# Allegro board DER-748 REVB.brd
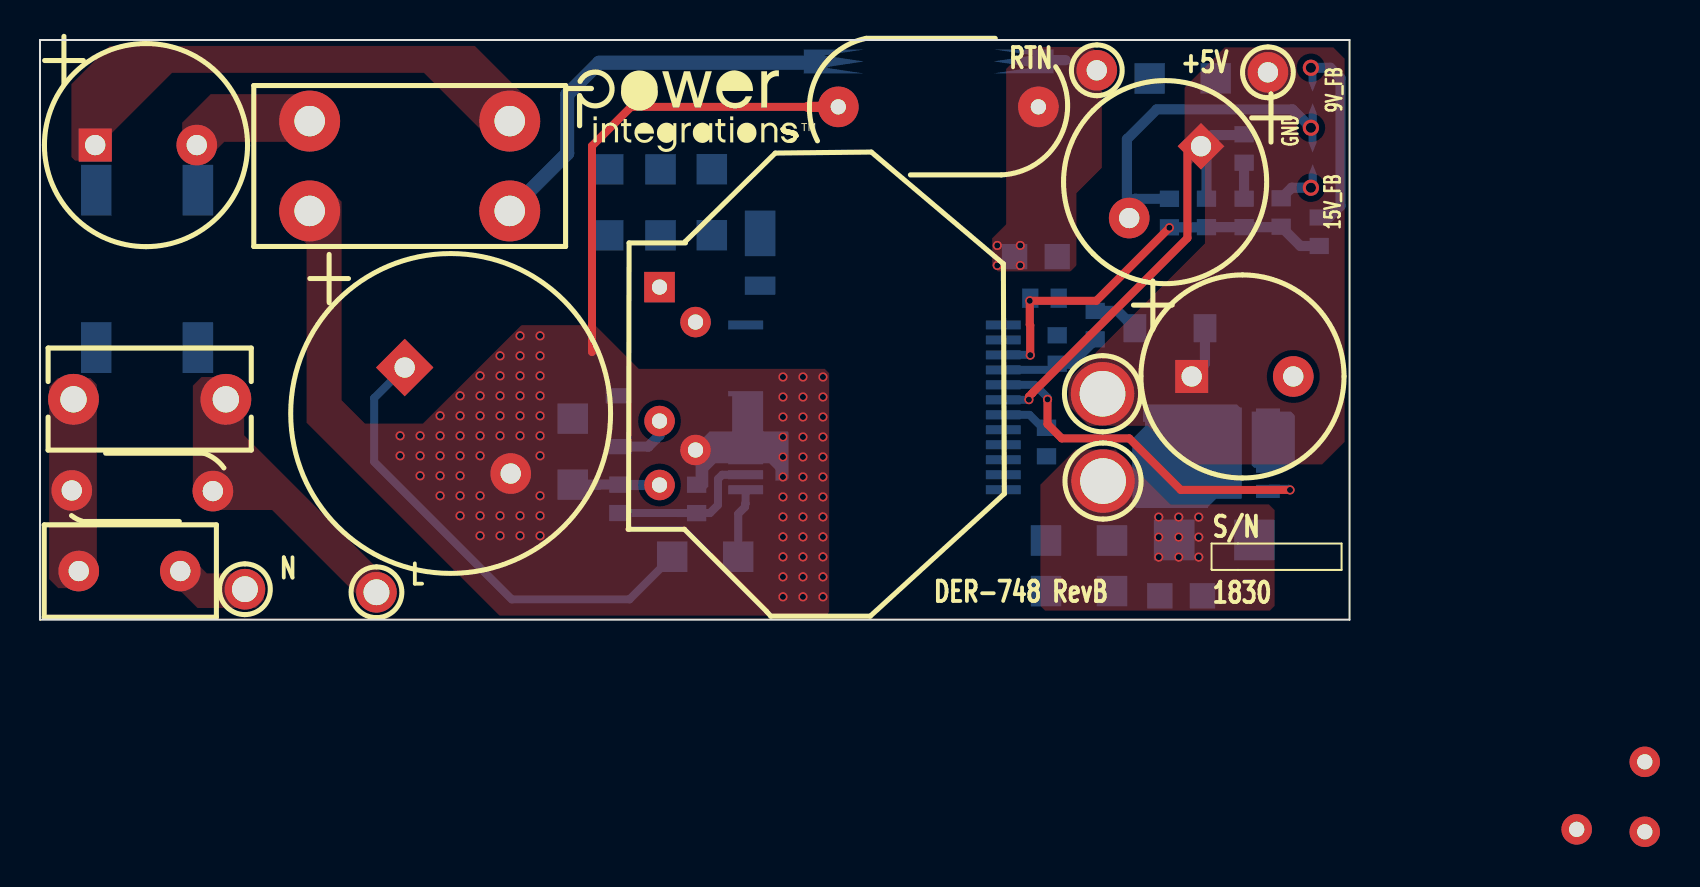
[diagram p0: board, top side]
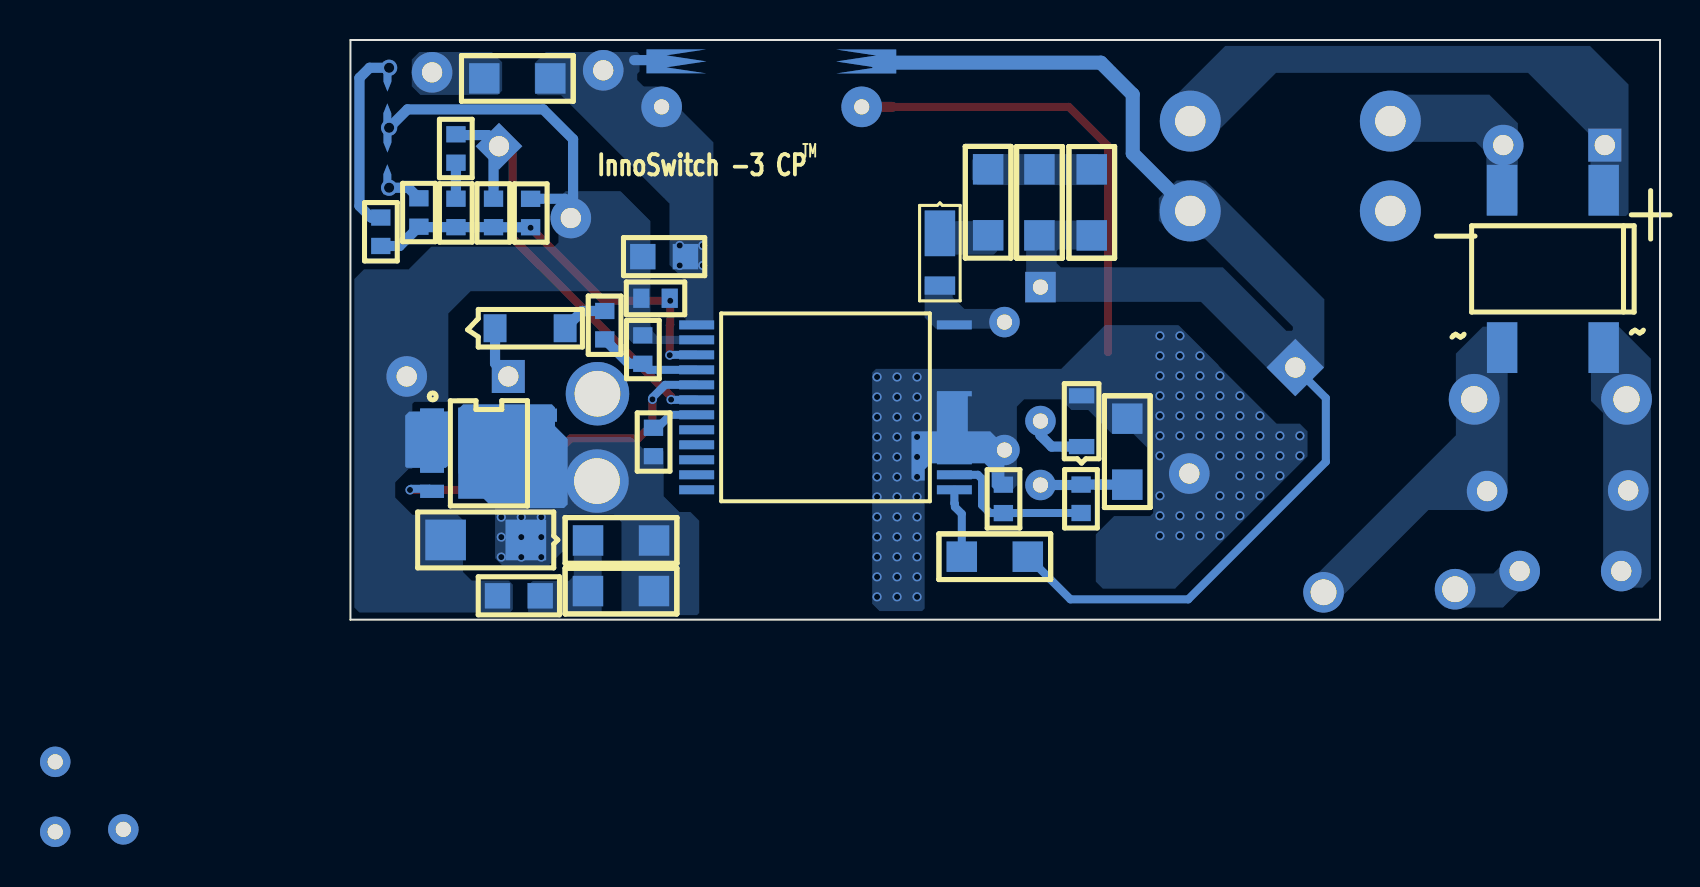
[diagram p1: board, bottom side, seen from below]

Outline 65.5 x 29 mm; copper layers: TOP, BOTTOM. Coordinates in mm from the lower left corner of the outline.
Outline path: 0,29 65.5,29 65.5,0 0,0 0,29

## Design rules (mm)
constraint set DEFAULT: min track width 0.508

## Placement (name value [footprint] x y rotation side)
BR1  DF206ST-G  [PISMDDFS]  2.82 21.43 180 bottom
C1  47 nF  [PI_NP395X200LS300D040]  9.3 11.02 180 top
C3  56 uF  [PIPOLCAPCLYD16D16H7P5LS040]  18.24 12.61 315 top
C5  0.47 uF  [PISMC0603]  32.84 5.33 90 bottom
C6  22 uf  [PISMC1206]  26.64 6.75 90 bottom
C7  2.2 nF  [PINPCAPRAD374X275LS394D030]  39.93 25.65 0 top
C8  2.2 nF  [PISMC0805]  56.01 1.19 0 bottom
C9  2.2 uF  [PISMC0603]  50.88 12.8 90 bottom
C11  330 pF  [PISMC0603]  50.95 16.08 180 bottom
C12  4.7 nF  [PISMC0603]  60.22 21.06 270 bottom
C13  10 uF  [PISMC1206]  58.8 27.08 180 bottom
C14  560 uF  [PIPOLCAPCYLD400LS200040]  58.07 23.68 225 top
C15  560 uF  [PIPOLCAPCYLD400LS200040]  57.6 12.17 0 top
C17  27 uF  [PIPOLCAPCYLD400LS200040]  2.76 23.74 0 top
C18  470 pF  [PISMC1206]  28.42 19.23 90 bottom
D1  DFLR1600  [PISMDDFLR120012]  36.02 19.35 90 bottom
D2  BAV21WS-7-F  [PISMSOD323]  28.93 8.66 90 bottom
D4  STPS2H100AY  [PISMDSMA]  56.73 3.99 0 bottom
F1  1 A  [PI_RST_MICROFUSE]  7.02 2.43 180 top
FL1  Hole_90  [PI_HOLE_70MIL]  53.14 11.28 0 top
FL2  Hole_90  [PI_HOLE_70MIL]  53.17 6.91 0 top
L1  10 mH  [PI_IND_4P_590X295LS394X177D060]  13.51 24.92 180 top
NOREF  -  []  65.5 0 90 top
NOREF#2  -  []  26.34 27.28 0 top
NOREF#3  -  []  -150.78 54.23 0 top
NOREF#4  -  []  0 29 0 top
NOREF#5  -  []  -228.6 -144.78 0 top
Q3  BSC028N06LS3GATMA1  [PI_SM_PG-TDSON-8]  61.42 10.23 270 bottom
R5  51  [PISMR1206]  33.6 22.53 270 bottom
R8  10 k  [PISMR0603]  28.96 6.76 270 bottom
R10  47  [PISMR0603]  50.34 8.18 90 bottom
R13  13  [PISMR1206]  50.32 3.96 0 bottom
R14  100 k  [PISMR0603]  58.34 21.06 270 bottom
R15  33 K  [PISMR0603]  56.49 19.63 90 bottom
R16  0.005  [PISMR0805]  50.88 18.16 180 bottom
R19  2.2M  [PISMR1206]  31.62 3.15 0 bottom
R21  200 k  [PISMR1206]  31.04 19.23 90 bottom
R22  32.4 k  [PISMR0603]  63.98 18.69 90 bottom
R23  12.4 k  [PISMR0603]  62.08 19.66 90 bottom
R24  0.0  [PISMR0603]  60.22 24.28 270 bottom
R25  1 k  [PISMR0603]  52.78 15.44 270 bottom
R26  13  [PISMR1206]  50.32 1.43 0 bottom
RV1  275 Vac  [PIDISC350X160LS210X140040]  8.65 6.43 210 top
T2  RM8  [PI_BOBBIN_RM8_8P]  30.99 16.64 0 top
TP1  L  [PITPKEYSTONE100X100]  16.83 1.37 0 top
TP2  N  [PITPKEYSTONE100X100]  10.25 1.52 0 top
TP10  RET  [PITPKEYSTONE100X100]  52.86 27.48 0 top
TP11  +5V  [PITPKEYSTONE100X100]  61.42 27.38 0 top
U1  INN3268C  [PI_IC_INSOP_24D]  48.18 14.75 180 bottom
VR1  MMSZ5245B  [PI_SM_SOD-123_12]  58.27 14.58 180 bottom

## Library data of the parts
BR1 = DIODE BRIDGE_+-~~
C1 C5-C9 C11-C13 C18 = CAP NP
C3 = CAP POL: alternate symbols: (pipolcapclyd16d16h7p5ls040h)
C14 C15 = CAP POL
C17 = CAP POL: alternate symbols: (pipolcapclyd400x675ls200040h)
D1 D2 = DIODE
D4 = DIODE SCHOTTKY
F1 = FUSE: alternate symbols: (pirstmicrofusehoz)
FL1 FL2 = FlyingLead
L1 = INDUCTOR_4P_revD
Q3 = FET_N_TSDSON-8
R5 R8 R10 R13-R16 R19 R21-R26 = R
RV1 = VARISTOR: alternate symbols: (pi_disc_354x220_ls220x10_040_h)
T2 = BRM8_8P/6-2
TP1 TP2 TP10 TP11 = TESTPOINT
U1 = DEV_InSOP_0
VR1 = DIODE_ZENER

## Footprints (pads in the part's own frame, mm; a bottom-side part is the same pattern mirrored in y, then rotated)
PI_BOBBIN_RM8_8P
  rect 1.524x1.524 hole 0.762: 1(0,0)
  round 1.524 hole 0.762: 2(1.8,-1.75) 3(45.872,-27.127) 4(0,-6.7) 5(1.8,-8.15) 6(0,-9.9) 7(49.278,-27.249) 8(49.278,-23.749)
PI_HOLE_70MIL
  round 3.175 hole 2.286: 1(0,0.025)
PI_IC_INSOP_24D
  rect 1.75x0.45 smd: 1(0,0) 2(0,-0.75) 3(0,-1.5) 4(0,-2.25) 5(0,-3) 6(0,-3.75) 7(0,-4.5) 8(0,-5.25) 9(0,-6) 10(0,-6.75) 11(0,-7.5) 12(0,-8.25) 13(12.89,-8.25) 14(12.89,-7.5) 15(12.89,-6.75) 24(12.89,0)
  custom 0.438x0.438 smd: 16(12.89,-4.67)
PI_IND_4P_590X295LS394X177D060
  round 3.048 hole 1.524: 1(0.025,-0.025) 2(0.025,4.47) 3(-9.982,4.47) 4(-9.982,-0.025)
PI_NP395X200LS300D040
  round 2.54 hole 1.321: 1(0,0) 2(7.62,0)
PI_RST_MICROFUSE
  round 2.032 hole 1.016: 1(0,0) 2(5.08,0)
PI_SM_PG-TDSON-8
  rect 0.66x1.194 smd: 1(0,0) 2(1.27,0) 3(2.54,0) 4(3.81,0) 5(3.81,5.65) 6(2.54,5.65) 7(1.27,5.65) 8(0,5.65)
PI_SM_SOD-123_12
  rect 1.143x1.397 smd: 1(0,0) 2(3.505,0)
PIDISC350X160LS210X140040
  round 2.032 hole 1.016: 1(0,0) 2(6.096,-3.556)
PINPCAPRAD374X275LS394D030
  round 2.032 hole 0.762: 1(0,0) 2(10.008,0)
PIPOLCAPCLYD16D16H7P5LS040
  rect 2.032x2.032 hole 1.016: 1(0,0)
  round 2.032 hole 1.016: 2(7.5,0)
PIPOLCAPCYLD400LS200040
  rect 1.651x1.651 hole 1.016: 1(0,0)
  round 2.032 hole 1.016: 2(5.08,0)
PISMC0603
  rect 0.813x0.965 smd: 1(0,0) 2(1.422,0)
PISMC0805
  rect 1.27x1.27 smd: 1(0,0) 2(2.134,0)
PISMC1206
  rect 1.524x1.524 smd: 1(0,0) 2(3.302,0)
PISMDDFLR120012
  rect 2.286x1.524 smd: 1(-0.025,0)
  rect 0.914x1.524 smd: 2(-2.642,0)
PISMDDFS
  rect 1.524x2.54 smd: 1(0,0.051) 2(-5.08,0.051) 3(0,-7.823) 4(-5.08,-7.823)
PISMDSMA
  rect 2.032x2.032 smd: 1(0,0) 2(4.013,0)
PISMR0603
  rect 0.813x0.965 smd: 1(0,0) 2(1.422,0)
PISMR0805
  rect 1.27x1.27 smd: 1(0,0) 2(2.134,0)
PISMR1206
  rect 1.524x1.524 smd: 1(0,0) 2(3.302,0)
PISMSOD323
  rect 0.762x1.27 smd: 1(0,0) 2(2.54,0)
PITPKEYSTONE100X100
  round 2.032 hole 1.295: 1(0,0)

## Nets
GND_POWER: C8.2 C9.2 C11.1 C14.2 C15.2 D4.2 Q3.1(S1) R15.2 R16.1 U1.2
GND_SIGNAL: C3.2 C5.2 C6.2 C7.1 D2.2 L1.2 T2.5 U1.16
D6: Q3.6
D7: Q3.7
D8: Q3.8
NC8: U1.8
NC9: U1.9
NC10: U1.10
NC11: U1.11
NC12: U1.12
NC15: U1.15
S2: Q3.2
S3: Q3.3
N11018979: C13.1 C14.1 C15.1 FL1.1 R14.1 R24.1 TP11.1 U1.6 VR1.1
N11018987: C7.2 C13.2 R16.2 TP10.1 U1.1
N11019023: R10.2 U1.7
N11019027: D4.1 FL2.1 Q3.5 R10.1 R13.1 R26.1
N11019129: Q3.4 U1.5
N11019153: D1.1 R5.2
N11019263: BR1.2 C17.2 L1.1
N11019293: C5.1 R8.2 U1.14
N11019397: BR1.4 C1.1 RV1.1 TP1.1
N11019401: C8.1 R13.2 R26.2
N11019569: C6.1 R8.1 T2.6
N11019593: R19.2 U1.13(VPIN)
N11019613: C3.1 C18.1 L1.3 R19.1 R21.1 T2.1
N11019673: BR1.3 C1.2 F1.2 RV1.2
N11019681: BR1.1 C17.1 L1.4
N11019743: C11.2 C12.2 R14.2 R15.1 R22.1 R23.1 U1.3
N11020702: C18.2 R5.1 R21.2
N11020753: D1.2 T2.2 U1.24
N11026403: F1.1 TP2.1
N11053934: D2.1 T2.4
N11096846: R22.2
N11102317: R23.2
N11111738: C12.1 R24.2
N11113310: C9.1 R25.2 U1.4
N11114484: R25.1 VR1.2

Pads without a net: T2 3 7 8

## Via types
v1: diameter 0.813, hole 0.508, TOP to BOTTOM, 3 vias
v2: diameter 0.457, hole 0.305, TOP to BOTTOM, 105 vias

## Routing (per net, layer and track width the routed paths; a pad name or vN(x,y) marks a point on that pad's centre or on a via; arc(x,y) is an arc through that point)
GND_POWER: length 17
  BOTTOM w0.508: v1(63.57,24.61) 62.65,25.53 55.85,25.53 54.37,24.04 54.37,20.21 C14.2 54.48,20.75 54.78,21.05 R15.2
GND_SIGNAL: length 23.4
  TOP w0.4: 38.4,25.65 29.57,25.65 27.61,23.7 27.61,13.39
  TOP w0.508: 38.4,25.65 C7.1
  vias: v2(18.01,9.2) v2(18.01,8.2) v2(19.01,9.2) v2(19.01,8.2) v2(19.01,7.2) v2(20.01,10.2) v2(20.01,9.2) v2(20.01,8.2) v2(20.01,7.2) v2(20.01,6.2) v2(21.01,11.2) v2(21.01,10.2) v2(21.01,9.2) v2(21.01,8.2) v2(21.01,7.2) v2(21.01,6.2) v2(21.01,5.2) v2(22.01,12.2) v2(22.01,11.2) v2(22.01,10.2) v2(22.01,9.2) v2(22.01,8.2) v2(22.01,6.2) v2(22.01,5.2) v2(22.01,4.2) v2(23.01,13.2) v2(23.01,12.2) v2(23.01,11.2) v2(23.01,10.2) v2(23.01,9.2) v2(23.01,5.2) v2(23.01,4.2) v2(24.01,14.2) v2(24.01,13.2) v2(24.01,12.2) v2(24.01,11.2) v2(24.01,10.2) v2(24.01,9.2) v2(24.01,5.2) v2(24.01,4.2) v2(25.01,14.2) v2(25.01,13.2) v2(25.01,12.2) v2(25.01,11.2) v2(25.01,10.2) v2(25.01,9.2) v2(25.01,8.2) v2(25.01,6.2) v2(25.01,5.2) v2(25.01,4.2) v2(37.16,12.14) v2(37.16,11.14) v2(37.16,10.14) v2(37.16,9.14) v2(37.16,8.14) v2(37.16,7.14) v2(37.16,6.14) v2(37.16,5.14) v2(37.16,4.14) v2(37.16,3.14) v2(37.16,2.14) v2(37.16,1.14) v2(38.16,12.14) v2(38.16,11.14) v2(38.16,10.14) v2(38.16,9.14) v2(38.16,8.14) v2(38.16,7.14) v2(38.16,6.14) v2(38.16,5.14) v2(38.16,4.14) v2(38.16,3.14) v2(38.16,2.14) v2(38.16,1.14) v2(39.16,12.14) v2(39.16,11.14) v2(39.16,10.14) v2(39.16,9.14) v2(39.16,8.14) v2(39.16,7.14) v2(39.16,6.14) v2(39.16,5.14) v2(39.16,4.14) v2(39.16,3.14) v2(39.16,2.14) v2(39.16,1.14)
N11018979: length 25.7
  TOP w0.4: v2(49.46,11.01) 49.46,11.16 49.63,11.33 49.63,11.34 57.39,19.09 57.39,23.67 57.41,23.68 C14.1
  BOTTOM w0.4: U1.6 49.45,11 v2(49.46,11.01)
  BOTTOM w0.508: VR1.1 58.27,12.82 57.62,12.17 C15.1 ; R24.1 60.17,24.28 60.13,24.24 58.63,24.24 C14.1 58.34,23.41 R14.1
N11018987: length 1.2
  BOTTOM w0.508: 50.09,27.99 51.31,27.99
  vias: v2(47.88,18.72) v2(47.88,17.72) v2(49.03,18.72) v2(49.03,17.72)
N11019023: length 2.4
  BOTTOM w0.4: U1.7 49.49,10.25 50.14,9.6 R10.2
N11019027:
  vias: v2(55.96,5.13) v2(55.96,4.13) v2(55.96,3.13) v2(56.96,5.13) v2(56.96,4.13) v2(56.96,3.13) v2(57.96,5.13) v2(57.96,4.13) v2(57.96,3.13)
N11019129: length 18.5
  TOP w0.4: v2(50.39,11.02) 50.39,9.78 51.1,9.07 54.48,9.07 57.06,6.49 v2(62.52,6.49)
  BOTTOM w0.4: v2(50.39,11.02) 50.39,11.11 49.76,11.75 U1.5 ; v2(62.52,6.49) 62.47,6.55 61.54,6.55 Q3.4
N11019293: length 7.9
  BOTTOM w0.4: U1.14 34.12,7.25 33.91,7.04 33.91,5.73 33.51,5.33 C5.1 31.91,5.33 31.9,5.34 R8.2
N11019569: length 4.4
  BOTTOM w0.508: C6.1 27.91,6.75 27.92,6.76 R8.1 28.98,6.74 T2.6
N11019593: length 3.5
  BOTTOM w0.4: U1.13 35.29,5.82 35.27,5.79 35.27,5.64 34.92,5.3 R19.2
N11019613: length 44.4
  BOTTOM w0.4: C3.1 16.71,11.09 16.71,7.9 23.6,1.02 29.49,1.02 R19.1
  BOTTOM w0.7: L1.3 26.37,23.32 26.37,26.27 27.97,27.86 39.14,27.86
N11019743: length 20.5
  TOP w0.4: v2(49.53,13.23) 49.53,14.73 49.5,14.76 v2(49.5,15.95) 52.84,15.95 v2(56.49,19.61)
  BOTTOM w0.4: U1.3 49.52,13.25 v2(49.53,13.23)
  BOTTOM w0.508: R15.1 58.14,19.63 58.14,19.64 R14.2 60.1,19.64 C12.2 62.06,19.64 R23.1 63.04,18.69 R22.1
N11053934: length 3
  BOTTOM w0.508: D2.1 30.43,8.66 30.99,9.22 T2.4
N11096846: length 9.4
  BOTTOM w0.508: v1(63.57,27.61) 64.54,27.61 65.05,27.1 65.05,20.7 64.47,20.12 R22.2
N11102317: length 1.7
  BOTTOM w0.508: v1(63.57,21.61) 62.61,21.61 R23.2
N11111738: length 1.8
  BOTTOM w0.508: C12.1 R24.2
N11113310: length 5.2
  BOTTOM w0.4: U1.4 50.57,12.5 C9.1
  BOTTOM w0.508: C9.1 51.56,12.8 R25.2
N11114484: length 2.3
  BOTTOM w0.508: VR1.2 53.9,15.44 R25.1

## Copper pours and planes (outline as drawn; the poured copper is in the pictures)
GND_POWER on BOTTOM (solid shape): 62.76,10.21 62.76,7.67 62.69,7.59 60.73,7.59 60.6,7.72 60.6,10.41 62.56,10.41
GND_POWER on BOTTOM (solid shape): 62.01,8.63 62.02,8.63 62.02,7.36 60.82,7.36 60.82,10.56 62.01,10.56
GND_POWER on BOTTOM: 62.4,5.25 63.26,6.11 63.26,6.87 62.59,7.54 62.41,7.54 62.41,10.79 62.31,10.9 60.6,10.9 60.6,15.32 59.49,16.43 51.92,16.43 51.64,16.15 51.64,14.1 51.33,13.79 47.88,13.79 47.85,13.82 47.85,14.12 47.93,14.2 50.16,14.2 50.47,14.5 50.47,14.67 50.5,14.69 50.5,19.94 51.99,21.44 54.74,21.44 55.09,21.08 55.09,18.87 55.31,18.66 61.46,18.66 62.59,17.53 64.82,17.53 65.3,17.04 65.3,0.61 65.05,0.36 57.53,0.36 57.38,0.51 57.38,1.75 57.58,1.96 59.44,1.96 59.87,2.39 59.87,4.98 60.13,5.25
GND_SIGNAL on BOTTOM (solid shape): 37.44,9.37 37.44,7.06 37.34,6.96 36.78,6.96 36.78,7.52 36.47,7.82 33.78,7.82 33.43,7.47 33.43,6.65 33.3,6.53 32.94,6.53 32.79,6.68 32.79,8.71 33.5,9.42 37.39,9.42
GND_SIGNAL on TOP: 39.47,12.32 39.47,0.38 39.29,0.2 22.99,0.2 13.34,9.86 13.34,18.8 12.04,20.09 12.04,21.08 12.57,21.62 14.38,21.62 15.09,20.9 15.09,10.97 16.26,9.8 19.15,9.8 24.08,14.73 27.76,14.73 29.95,12.55 39.24,12.55
GND_SIGNAL on BOTTOM: 33.43,8.36 33.43,6.65 33.25,6.48 32.41,6.48 32.17,6.72 32.17,10.66 31.8,11.02 29.97,11.02 29.44,10.49 28.6,10.49 27.41,9.3 26.34,9.3 25.35,8.31 25.35,5.33 25.5,5.18 27.3,5.18 28.22,4.27 28.22,1.91 27.86,1.55 24.26,1.55 17.63,8.18 17.63,9.42 18.01,9.8 19.18,9.8 22.07,12.7 22.07,12.73 24.08,14.73 27.76,14.73 29.95,12.55 39.22,12.55 39.41,12.36 39.41,0.8 39.04,0.43 36.91,0.43 36.78,0.56 36.78,8.51 36.53,8.76 33.83,8.76
D8 on BOTTOM (solid shape): 60.11,6.05 55.72,6.05 55.72,10.61 60.11,10.61
N11018979 on TOP: 58.27,18.82 58.27,22.73 58.04,22.96 57.76,22.96 57.51,22.71 57.38,22.71 57.25,22.83 57.25,26.62 59.26,28.63 64.69,28.63 65.25,28.07 65.25,8.89 64.14,7.77 57.33,7.77 55.4,9.7 52.45,9.7 51.44,10.72 51.44,11.99
N11018979 on BOTTOM: 57.91,27.89 57.91,26.47 58.13,26.25 62,26.25 62.43,26.68 62.43,28.02 62.05,28.4 58.42,28.4
N11018987 on BOTTOM (solid shape): 50.7,27.33 47.7,27.33 49.7,27.63 47.7,27.93 49.7,28.23 47.7,28.53 50.7,28.53
N11018987 on TOP: 52.6,28.65 49.43,28.65 48.32,27.55 48.32,19.77 47.62,19.08 47.62,17.7 47.9,17.42 51.54,17.42 51.84,17.73 51.84,21.34 53.11,22.61 53.11,28.14
N11018987 on BOTTOM: 47.35,23.88 50.14,26.67 50.83,26.67 51.16,27 51.16,27.3 51.04,27.42 51.04,28.28 51.16,28.4 55.73,28.4 56.29,27.84 56.29,26.39 56.13,26.24 54.97,26.24 49.54,20.82 49.54,17.74 48.74,16.94 48.74,14.66 48.62,14.53 47.55,14.53 47.35,14.73
N11019027 on BOTTOM (solid shape): 60.1,10.54 60.1,7.32 58.42,5.64 58.42,5.59 54.81,5.59 54.64,5.77 54.64,9.04 55.27,9.68 55.27,10.62 55.42,10.77 59.87,10.77
N11019027 on TOP: 56.54,5.77 53.8,8.51 51.79,8.51 50.04,6.76 50.04,0.69 50.27,0.46 61.52,0.46 61.75,0.69 61.75,5.49 61.47,5.77
N11019027 on BOTTOM: 51.44,9.12 50.88,8.56 49.99,8.56 49.83,8.41 49.83,6.17 49.05,5.38 48.49,5.38 48.06,4.95 48.06,0.33 48.16,0.23 51.82,0.23 51.94,0.36 51.94,4.88 52.32,5.26 54.66,5.26 54.89,5.03 54.89,3.4 55.65,2.64 57.84,2.64 58.27,3.07 58.27,5.79 54.81,5.79 54.76,5.84 54.76,9.12
N11019153 on BOTTOM: 36.65,19.94 36.65,18.39 36.53,18.26 33.32,18.26 32.97,18.62 32.97,19.94
N11019263 on TOP: 14.05,26.29 8.53,26.29 7.11,24.87 7.11,23.14 7.37,22.89 8.2,22.89 9.22,23.9 14.07,23.9 14.66,24.49 14.66,25.68
N11019263 on BOTTOM: 8.53,26.26 14.07,26.26 14.66,25.68 14.66,24.49 14.07,23.9 9.22,23.9 8.69,23.37 8.69,20.22 7.24,20.22 7.11,20.35 7.11,24.84
N11019397 on TOP: 7.65,6.32 7.65,11.71 8.08,12.14 9.88,12.14 10.21,11.81 10.21,9.22 17.75,1.68 17.75,1.24 17.25,0.74 16.36,0.74 11.61,5.49 8.48,5.49
N11019397 on BOTTOM: 7.62,14.58 7.62,6.32 8.46,5.49 11.58,5.49 16.33,0.74 17.27,0.74 17.75,1.22 17.75,1.68 10.21,9.22 10.21,13.31 8.86,14.66 7.7,14.66
N11019401 on BOTTOM: 52.93,4.67 52.93,0.38 53.06,0.25 56.46,0.25 56.62,0.41 56.62,1.7 56.39,1.93 54.58,1.93 54.33,2.18 54.33,4.62 54.23,4.72 52.98,4.72
N11019613 on BOTTOM (solid shape): 39.2,28.22 41.2,27.92 39.2,27.62 41.2,27.32 38.2,27.32 38.2,28.52 41.2,28.52
N11019613 on BOTTOM: 31.55,15.9 31.7,16.05 31.7,19.66 31.39,19.96 27.89,19.96 27.7,19.77 27.7,18.63 27.81,18.52 30.1,18.52 30.18,18.44 30.18,17.83 29.97,17.63 21.87,17.63 18.69,14.45 18.41,14.45 18.36,14.5 18.36,14.66 22.75,19.04 24.14,19.04 25.07,19.96 25.07,21.08 24.18,21.97 22.73,21.97 16.79,16.03 16.79,12.65 17.96,11.48 18.54,11.48 22.96,15.9
N11019673 on TOP: 2.46,1.57 0.91,1.57 0.46,2.03 0.46,11.66 0.89,12.09 2.51,12.09 2.84,11.76 2.84,1.96
N11019673 on BOTTOM: 0.46,2.03 0.89,1.6 2.49,1.6 2.84,1.96 2.84,10.34 3.45,10.95 3.45,14.76 3.38,14.83 2.24,14.83 0.46,13.06
N11019681 on TOP: 3.45,24.21 3.45,23.22 3.2,22.96 1.75,22.96 1.57,23.14 1.57,26.8 3.48,28.7 21.74,28.7 24.66,25.78 24.66,24.21 24.23,23.77 22.78,23.77 19.2,27.36 6.6,27.36
N11019681 on BOTTOM: 1.7,20.19 1.57,20.32 1.57,26.77 3.51,28.7 21.74,28.7 24.66,25.78 24.66,24.21 24.23,23.77 22.78,23.77 19.2,27.36 6.6,27.36 3.48,24.23 3.48,20.19
N11020702 on BOTTOM: 27.86,23.01 27.86,22.05 28.17,21.74 34.14,21.74 34.42,22.02 34.42,22.99 34.11,23.29 28.14,23.29
N11020753 on BOTTOM: 32.56,14.55 36.22,14.55 36.78,15.11 36.78,17.04 36.68,17.14 35.38,17.14 35.38,16.13 34.8,15.54 32.64,15.54 32.26,15.16 32.26,14.86
N11026403 on TOP: 7.44,3.23 6.45,3.23 6.22,3 6.22,2.24 7.87,0.58 10.79,0.58 11.2,0.99 11.2,1.88 10.77,2.31 8.36,2.31
N11026403 on BOTTOM: 10.74,2.31 8.33,2.31 7.42,3.23 6.5,3.23 6.22,2.95 6.22,2.24 7.85,0.61 10.77,0.61 11.23,1.07 11.23,1.83

Small or netless copper shapes (teardrops, artwork), in the pictures only: 4 on BOTTOM

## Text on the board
Ref Des/Silkscreen Bottom: TM | InnoSwitch -3 CP
User.Comments: 10 | 13 | /16 | 25 | 20 | NG | 7
Ref Des/Silkscreen Top: GND | 15V_FB | 9V_FB | N | L | DER-748 RevB | RTN | +5V | S/N | 1830
User.6: 14.  FAB HOUSE LOGO,DATE CODE TO BE IN SILK SCREEN ONLY.DO NOT USE COPPER. | 13.  MATERIAL FR4 COPPER 2oz THICKNESS 0.062"
User.8: FIGURE | FINISHED_SIZE | 0.3048 | 0.508 | 0.762 | 1.016 | 1.2954 | 1.3208 | 1.524 | 2.286 | DRILL CHART: TOP to BOTTOM | ALL UNITS ARE IN MILLIMETERS | PLATED | QTY | 105 | 3 | 10 | 14 | 2 | 4
